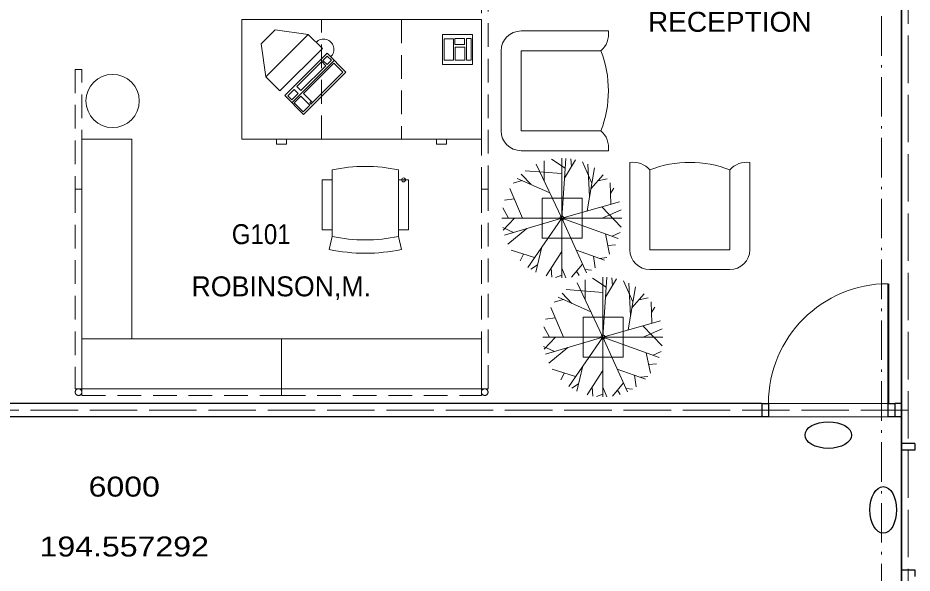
# Model space of a CAD drawing. Extents: x -118748 to -117136, y -118748 to -117596.
# Drawn here: x -117681.9 to -117467, y -118332.8 to -118199.3 of the extents above; entities that cross this region are included whole.
import ezdxf
from ezdxf.enums import TextEntityAlignment as Align

# ---------------------------------------------------------------- set-up
doc = ezdxf.new("R2010")
doc.units = 0
doc.header["$LTSCALE"] = 1.9
doc.header["$PDMODE"] = 32
doc.header["$PDSIZE"] = 0.95
for name, pattern in [('DOT_DASHED', [7.7, 5, -1.2, 0.3, -1.2]), ('LONG_DASHED', [7.5, 6, -1.5]), ('MEDIUM_DASHED', [4.5, 3, -1.5])]:
    doc.linetypes.add(name, pattern=pattern)
for name, color, linetype, lineweight in [('10', 7, 'DOT_DASHED', 13), ('15', 7, 'Continuous', 13), ('16', 7, 'Continuous', 13), ('20', 7, 'MEDIUM_DASHED', 13), ('23', 7, 'Continuous', 25), ('25', 7, 'Continuous', 13), ('26', 7, 'Continuous', 25), ('30', 7, 'Continuous', 13), ('4', 7, 'Continuous', 35), ('42', 7, 'Continuous', 25), ('45', 7, 'Continuous', 25), ('5', 7, 'Continuous', 13), ('6', 7, 'Continuous', 13), ('60', 7, 'LONG_DASHED', 13), ('9', 7, 'Continuous', 35)]:
    doc.layers.add(name, color=color, linetype=linetype, lineweight=lineweight)
doc.layers.add('53', color=7, linetype='Continuous')

msp = doc.modelspace()

# ---------------------------------------------------------------- linework, layer by layer
at = {"layer": '10'}
msp.add_line((-117474.321, -117628.339), (-117474.321, -118698.41), dxfattribs=at)
at = {"layer": '15'}
for p, q in [((-117560.955, -118202.433), (-117539.969, -118202.433)), ((-117565.755, -118226.433), (-117565.755, -118207.233)), ((-117539.969, -118231.233), (-117560.955, -118231.233)), ((-117534.803, -118255.029), (-117534.803, -118234.044)), ((-117506.003, -118234.044), (-117506.003, -118255.029)), ((-117606.387, -118235.846), (-117606.387, -118251.846)), ((-117590.387, -118235.846), (-117590.387, -118251.846)), ((-117608.787, -118238.246), (-117608.787, -118250.246)), ((-117608.787, -118238.246), (-117606.387, -118238.246)), ((-117606.387, -118238.246), (-117606.387, -118250.246)), ((-117590.387, -118238.246), (-117590.387, -118250.246)), ((-117590.387, -118238.246), (-117587.987, -118238.246)), ((-117587.987, -118238.246), (-117587.987, -118250.246)), ((-117606.387, -118250.246), (-117608.787, -118250.246)), ((-117587.987, -118250.246), (-117590.387, -118250.246)), ((-117606.387, -118251.846), (-117607.064, -118254.974)), ((-117590.387, -118251.846), (-117589.711, -118254.974)), ((-117510.803, -118259.829), (-117530.003, -118259.829))]:
    msp.add_line(p, q, dxfattribs=at)
for points in [[(-117570.495, -118228.479), (-117570.495, -118199.679), (-117628.095, -118199.679), (-117628.095, -118228.479)], [(-117666.495, -118276.479), (-117654.495, -118276.479), (-117654.495, -118228.479), (-117666.495, -118228.479)], [(-117618.495, -118288.479), (-117618.495, -118276.479), (-117666.495, -118276.479), (-117666.495, -118288.479)], [(-117570.495, -118288.479), (-117570.495, -118276.479), (-117618.495, -118276.479), (-117618.495, -118288.479)]]:
    msp.add_lwpolyline(points, close=True, dxfattribs=at)
for points in [[(-117541.755, -118226.433), (-117560.955, -118226.433), (-117560.955, -118207.233), (-117541.755, -118207.233)], [(-117510.803, -118235.829), (-117510.803, -118255.029), (-117530.003, -118255.029), (-117530.003, -118235.829)]]:
    msp.add_lwpolyline(points, dxfattribs=at)
for centre, radius, start, end in [((-117560.955, -118207.233), 4.8, 90, 180), ((-117545.447, -118203.128), 5.521, 311.96294, 7.22666), ((-117566.668, -118216.833), 26.699, 338.92678, 21.07322), ((-117560.955, -118226.433), 4.8, 180, 270), ((-117545.447, -118230.539), 5.521, 352.77334, 48.03706), ((-117534.108, -118239.521), 5.521, 41.96294, 97.22666), ((-117520.403, -118260.743), 26.699, 68.92678, 111.07322), ((-117506.697, -118239.521), 5.521, 82.77334, 138.03706), ((-117598.387, -118272.854), 37.863, 77.80217, 102.19782), ((-117598.387, -118214.838), 37.863, 257.80217, 282.19783), ((-117598.387, -118214.838), 37.863, 257.80217, 282.19783), ((-117598.387, -118214.838), 41.063, 257.80217, 282.19783), ((-117530.003, -118255.029), 4.8, 180, 270), ((-117510.803, -118255.029), 4.8, 270, 0)]:
    msp.add_arc(centre, radius, start, end, dxfattribs=at)
msp.add_point((-117589.187, -118238.246), dxfattribs=at)
at = {"layer": '16'}
for p, q in [((-117620.017, -118202.155), (-117623.411, -118205.549)), ((-117612.097, -118203.286), (-117620.017, -118202.155)), ((-117622.279, -118213.469), (-117623.411, -118205.549)), ((-117605.874, -118209.509), (-117616.057, -118219.691))]:
    msp.add_line(p, q, dxfattribs=at)
for points in [[(-117608.703, -118206.68), (-117612.097, -118203.286), (-117622.279, -118213.469), (-117618.885, -118216.863)], [(-117572.605, -118210.495), (-117572.605, -118203.295), (-117579.805, -118203.295), (-117579.805, -118210.495)], [(-117577.224, -118204.33), (-117577.224, -118209.447), (-117579.429, -118209.447), (-117579.429, -118204.33)], [(-117574.561, -118204.247), (-117574.561, -118205.703), (-117576.85, -118205.703), (-117576.85, -118204.247)], [(-117574.062, -118209.489), (-117574.062, -118204.247), (-117572.98, -118204.247), (-117572.98, -118209.489)], [(-117574.478, -118206.368), (-117574.478, -118209.489), (-117576.766, -118209.489), (-117576.766, -118206.368)], [(-117603.046, -118212.337), (-117607.572, -118207.812), (-117617.754, -118217.994), (-117613.228, -118222.52)], [(-117606.547, -118209.484), (-117607.547, -118208.483), (-117608.577, -118209.513), (-117607.577, -118210.513)], [(-117607.871, -118210.807), (-117608.871, -118209.807), (-117614.844, -118215.78), (-117613.843, -118216.78)], [(-117605.959, -118210.19), (-117603.811, -118212.337), (-117611.107, -118219.634), (-117613.255, -118217.486)], [(-117614.49, -118217.486), (-117615.461, -118216.515), (-117616.991, -118218.045), (-117616.02, -118219.016)], [(-117613.873, -118218.104), (-117611.696, -118220.281), (-117613.284, -118221.87), (-117615.462, -118219.692)], [(-117611.107, -118219.634), (-117611.372, -118219.369), (-117611.754, -118219.751), (-117611.49, -118220.016)]]:
    msp.add_lwpolyline(points, close=True, dxfattribs=at)
msp.add_arc((-117608.429, -118206.894), 2.497, 314.02184, 135.97816, dxfattribs=at)
at = {"layer": '20'}
for points in [[(-117570.495, -118240.479), (-117568.895, -118240.479), (-117568.895, -118192.479), (-117570.495, -118192.479)], [(-117668.095, -118240.479), (-117666.495, -118240.479), (-117666.495, -118211.679), (-117668.095, -118211.679)], [(-117668.095, -118288.479), (-117666.495, -118288.479), (-117666.495, -118240.479), (-117668.095, -118240.479)], [(-117570.495, -118288.479), (-117568.895, -118288.479), (-117568.895, -118240.479), (-117570.495, -118240.479)], [(-117618.495, -118290.079), (-117618.495, -118288.479), (-117666.495, -118288.479), (-117666.495, -118290.079)], [(-117570.495, -118290.079), (-117570.495, -118288.479), (-117618.495, -118288.479), (-117618.495, -118290.079)]]:
    msp.add_lwpolyline(points, close=True, dxfattribs=at)
for centre in [(-117667.295, -118289.279), (-117569.695, -118289.279)]:
    msp.add_circle(centre, 0.8, dxfattribs=at)
at = {"layer": '23'}
for p, q in [((-117469.521, -118292.01), (-117469.521, -118180.01)), ((-117503.121, -118292.01), (-117839.871, -118292.01)), ((-117503.121, -118292.01), (-117503.121, -118295.21)), ((-117471.121, -118292.01), (-117471.121, -118295.21)), ((-117469.521, -118292.01), (-117471.121, -118292.01)), ((-117503.121, -118295.21), (-117843.071, -118295.21)), ((-117469.521, -118295.21), (-117471.121, -118295.21)), ((-117466.321, -118301.61), (-117469.521, -118301.61))]:
    msp.add_line(p, q, dxfattribs=at)
at = {"layer": '23', "lineweight": 35}
msp.add_line((-117469.521, -118301.61), (-117469.521, -118295.21), dxfattribs=at)
at = {"layer": '23', "linetype": 'MEDIUM_DASHED', "lineweight": 13}
for points in [[(-117608.895, -118228.479), (-117608.895, -118199.679), (-117628.095, -118199.679), (-117628.095, -118228.479)], [(-117570.495, -118228.479), (-117570.495, -118199.679), (-117589.695, -118199.679), (-117589.695, -118228.479)], [(-117617.295, -118228.479), (-117617.295, -118229.679), (-117619.695, -118229.679), (-117619.695, -118228.479)], [(-117578.895, -118228.479), (-117578.895, -118229.679), (-117581.295, -118229.679), (-117581.295, -118228.479)]]:
    msp.add_lwpolyline(points, close=True, dxfattribs=at)
at = {"layer": '25', "lineweight": 40}
msp.add_line((-117472.721, -118263.21), (-117472.721, -118292.01), dxfattribs=at)
at = {"layer": '25'}
msp.add_arc((-117472.721, -118292.01), 28.8, 89.99998, 179.99998, dxfattribs=at)
at = {"layer": '26'}
for points in [[(-117503.121, -118292.01), (-117501.521, -118292.01), (-117501.521, -118295.21), (-117503.121, -118295.21)], [(-117471.121, -118295.21), (-117472.721, -118295.21), (-117472.721, -118292.01), (-117471.121, -118292.01)], [(-117466.321, -118301.61), (-117466.321, -118303.21), (-117469.521, -118303.21), (-117469.521, -118301.61)], [(-117469.521, -118333.61), (-117469.521, -118332.01), (-117466.321, -118332.01), (-117466.321, -118333.61)]]:
    msp.add_lwpolyline(points, dxfattribs=at)
at = {"layer": '30'}
for p, q in [((-117551.151, -118247.436), (-117557.334, -118234.431)), ((-117555.401, -118238.496), (-117555.398, -118233.677)), ((-117550.342, -118235.423), (-117553.612, -118233.248)), ((-117551.151, -118261.836), (-117551.151, -118233.036)), ((-117551.151, -118247.436), (-117550.183, -118233.069)), ((-117550.505, -118237.85), (-117547.865, -118233.416)), ((-117548.825, -118235.028), (-117548.997, -118233.198)), ((-117543.925, -118239.007), (-117546.188, -118233.918)), ((-117544.481, -118242.261), (-117544.899, -118234.464)), ((-117551.151, -118236.715), (-117559.946, -118236.035)), ((-117545.073, -118245.727), (-117543.302, -118235.363)), ((-117560.704, -118238.415), (-117562.876, -118239.077)), ((-117554.032, -118241.375), (-117561.92, -118237.876)), ((-117558.567, -118239.363), (-117560.934, -118236.869)), ((-117544.169, -118240.436), (-117541.211, -118237.017)), ((-117542.498, -118238.505), (-117540.292, -118237.979)), ((-117560.582, -118247.436), (-117563.676, -118240.331)), ((-117539.344, -118244.115), (-117539.527, -118238.936)), ((-117539.436, -118241.52), (-117538.695, -118240.211)), ((-117562.584, -118242.838), (-117564.902, -118243.164)), ((-117563.988, -118247.436), (-117565.343, -118244.998)), ((-117551.151, -118247.436), (-117537.289, -118243.537)), ((-117541.511, -118244.725), (-117536.911, -118249.579)), ((-117541.469, -118247.436), (-117536.891, -118245.435)), ((-117536.751, -118247.436), (-117565.551, -118247.436)), ((-117562.554, -118247.436), (-117565.254, -118250.344)), ((-117551.151, -118247.436), (-117564.959, -118251.522)), ((-117551.151, -118247.436), (-117559.331, -118259.287)), ((-117551.151, -118247.436), (-117545.249, -118260.571)), ((-117551.151, -118247.436), (-117537.604, -118252.32)), ((-117562.766, -118250.873), (-117565.374, -118249.688)), ((-117559.582, -118249.931), (-117564.116, -118253.702)), ((-117540.701, -118251.204), (-117539.666, -118256.123)), ((-117539.081, -118251.788), (-117537.173, -118250.895)), ((-117557.691, -118256.911), (-117563.301, -118255.165)), ((-117555.939, -118254.373), (-117557.401, -118260.409)), ((-117551.151, -118255.504), (-117554.943, -118261.328)), ((-117547.674, -118255.175), (-117540.897, -118257.547)), ((-117540.104, -118254.043), (-117538.271, -118253.876)), ((-117560.379, -118256.075), (-117561.209, -118257.742)), ((-117543.569, -118256.612), (-117543.147, -118259.407)), ((-117542.127, -118257.116), (-117540.327, -118256.934)), ((-117556.976, -118258.656), (-117558.638, -118259.737)), ((-117553.725, -118259.457), (-117553.547, -118261.635)), ((-117551.151, -118259.448), (-117550.215, -118261.806)), ((-117546.187, -118258.484), (-117548.87, -118261.655)), ((-117547.621, -118260.179), (-117546.99, -118261.222)), ((-117545.599, -118259.793), (-117544.014, -118259.943)), ((-117551.151, -118261.17), (-117552.666, -118261.756)), ((-117545.554, -118267.102), (-117545.551, -118262.283)), ((-117540.494, -118264.028), (-117543.765, -118261.854)), ((-117541.303, -118290.442), (-117541.303, -118261.642)), ((-117541.303, -118276.042), (-117540.336, -118261.674)), ((-117540.658, -118266.456), (-117538.017, -118262.022)), ((-117538.977, -118263.633), (-117539.149, -118261.804)), ((-117541.303, -118276.042), (-117547.486, -118263.037)), ((-117534.077, -118267.612), (-117536.341, -118262.524)), ((-117535.226, -118274.332), (-117533.454, -118263.969)), ((-117534.633, -118270.867), (-117535.051, -118263.07)), ((-117544.185, -118269.981), (-117552.072, -118266.482)), ((-117548.72, -118267.969), (-117551.086, -118265.475)), ((-117541.303, -118265.32), (-117550.099, -118264.64)), ((-117534.321, -118269.042), (-117531.363, -118265.623)), ((-117532.651, -118267.111), (-117530.444, -118266.585)), ((-117550.857, -118267.021), (-117553.028, -118267.682)), ((-117529.497, -118272.721), (-117529.68, -118267.542)), ((-117529.588, -118270.126), (-117528.847, -118268.817)), ((-117550.734, -118276.042), (-117553.829, -118268.937)), ((-117552.737, -118271.443), (-117555.055, -118271.769)), ((-117541.303, -118276.042), (-117527.441, -118272.143)), ((-117554.14, -118276.042), (-117555.495, -118273.604)), ((-117531.664, -118273.331), (-117527.064, -118278.185)), ((-117531.622, -118276.042), (-117527.043, -118274.04)), ((-117526.903, -118276.042), (-117555.703, -118276.042)), ((-117552.706, -118276.042), (-117555.407, -118278.95)), ((-117541.303, -118276.042), (-117555.111, -118280.128)), ((-117541.303, -118276.042), (-117549.484, -118287.893)), ((-117541.303, -118276.042), (-117535.402, -118289.177)), ((-117541.303, -118276.042), (-117527.757, -118280.926)), ((-117552.919, -118279.479), (-117555.526, -118278.293)), ((-117549.734, -118278.537), (-117554.269, -118282.307)), ((-117529.234, -118280.393), (-117527.325, -118279.501)), ((-117530.854, -118279.809), (-117529.818, -118284.728)), ((-117547.844, -118285.517), (-117553.454, -118283.77)), ((-117546.092, -118282.979), (-117547.554, -118289.015)), ((-117537.826, -118283.78), (-117531.05, -118286.152)), ((-117530.256, -118282.648), (-117528.424, -118282.482)), ((-117550.531, -118284.68), (-117551.361, -118286.347)), ((-117541.303, -118284.11), (-117545.095, -118289.934)), ((-117533.721, -118285.217), (-117533.299, -118288.012)), ((-117532.279, -118285.722), (-117530.48, -118285.539)), ((-117547.129, -118287.261), (-117548.791, -118288.342)), ((-117543.877, -118288.063), (-117543.7, -118290.241)), ((-117541.303, -118288.054), (-117540.367, -118290.411)), ((-117536.339, -118287.09), (-117539.023, -118290.26)), ((-117541.303, -118289.775), (-117542.818, -118290.362)), ((-117537.774, -118288.785), (-117537.143, -118289.828)), ((-117535.751, -118288.399), (-117534.167, -118288.549))]:
    msp.add_line(p, q, dxfattribs=at)
for points in [[(-117546.308, -118252.284), (-117546.308, -118242.684), (-117555.908, -118242.684), (-117555.908, -118252.284)], [(-117536.46, -118280.89), (-117536.46, -118271.29), (-117546.06, -118271.29), (-117546.06, -118280.89)]]:
    msp.add_lwpolyline(points, close=True, dxfattribs=at)
msp.add_circle((-117659.105, -118219.269), 6.4, dxfattribs=at)
for p in [(-117551.151, -118247.436), (-117541.303, -118276.042)]:
    msp.add_point(p, dxfattribs=at)
at = {"layer": '4'}
msp.add_lwpolyline([(-118496.721, -117964.01), (-118496.721, -118636.01), (-118271.121, -118636.01), (-118271.121, -118588.01), (-118115.969, -118588.01), (-118106.1, -118586.234), (-118096.66, -118581.314), (-118089.115, -118573.804), (-118084.156, -118564.399), (-118081.154, -118548.633), (-118079.134, -118548.633), (-117884.057, -118548.587), (-117881.646, -118565.336), (-117876.897, -118574.111), (-117869.271, -118581.538), (-117859.789, -118586.351), (-117850.271, -118588.01), (-117695.121, -118588.01), (-117695.121, -118636.01), (-117469.521, -118636.01), (-117469.521, -117964.01)], close=True, dxfattribs=at)
at = {"layer": '42'}
for centre, major_axis in [((-117487.121, -118299.61), (-5.6, 0)), ((-117473.921, -118317.61), (0, -5.6))]:
    msp.add_ellipse(centre, major_axis=major_axis, ratio=0.571429, dxfattribs=at)
at = {"layer": '5'}
for points in [[(-117981.521, -118118.36), (-117981.521, -117964.01), (-117469.521, -117964.01), (-117469.521, -117992.81), (-117469.521, -118180.01), (-117469.521, -118292.01), (-117839.871, -118292.01), (-117839.871, -118184.81)], [(-117979.078, -117964.01), (-117469.521, -117964.01), (-117469.521, -118636.01), (-117695.121, -118636.01), (-117695.121, -118588.01), (-117850.271, -118588.01)], [(-117843.071, -118184.81), (-117843.071, -118295.21), (-117503.121, -118295.21), (-117469.521, -118295.21), (-117469.521, -118301.61), (-117469.521, -118343.21), (-117479.121, -118343.21), (-117698.321, -118343.21), (-117698.321, -118357.61), (-117698.321, -118420.01), (-117843.25, -118420.01)]]:
    msp.add_lwpolyline(points, dxfattribs=at)
at = {"layer": '6'}
msp.add_lwpolyline([(-117981.521, -117964.01), (-117469.521, -117964.01), (-117469.521, -118292.01), (-117839.871, -118292.01), (-117839.871, -118184.81)], dxfattribs=at)
msp.add_lwpolyline([(-117843.071, -118295.21), (-117469.521, -118295.21), (-117469.521, -118343.21), (-117843.071, -118343.21)], close=True, dxfattribs=at)
at = {"layer": '60'}
for p, q in [((-117467.921, -118343.21), (-117467.921, -118180.01)), ((-117467.921, -118293.61), (-117841.784, -118293.61))]:
    msp.add_line(p, q, dxfattribs=at)

# ---------------------------------------------------------------- texts
at = {"layer": '45', "width": 1.2}
for s, p in [('6000', (-117656.315, -118314.41)), ('194.557292', (-117656.315, -118328.81))]:
    msp.add_text(s, height=4.8, dxfattribs=at).set_placement(p, align=Align.CENTER)
at = {"layer": '53', "width": 1.05}
msp.add_text('RECEPTION', height=4.8, dxfattribs=at).set_placement((-117530.466, -118202.638))
at = {"layer": '53'}
msp.add_text('ROBINSON,M.', height=4.8, dxfattribs=at).set_placement((-117640.147, -118266.253))
at = {"layer": '9', "width": 0.9}
msp.add_text('G101', height=4.8, dxfattribs=at).set_placement((-117623.398, -118253.704), align=Align.CENTER)

doc.saveas('drawing.dxf')
